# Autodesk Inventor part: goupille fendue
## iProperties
Created: 2002-04
Part Number: goupille fendue
Material: Par défaut
Document SubType Name: Modélisation
Designer: thchene
Control State: 0
Master: False
Checked Out: False
Shininess: 20.0
Angle Display Precision: 2
Document Length Units: 11269
Document Angle Units: 11279
Document Time Units: 11290
Document Mass Units: 11283
Document Length Units Precision: 3
Document Angle Units Precision: 2
Compacted: True
Density: 0.0
Volumn: 0.0
Area: 0.0
PropertySet Name: Model Information
Author: thchene
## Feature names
1. Base1
